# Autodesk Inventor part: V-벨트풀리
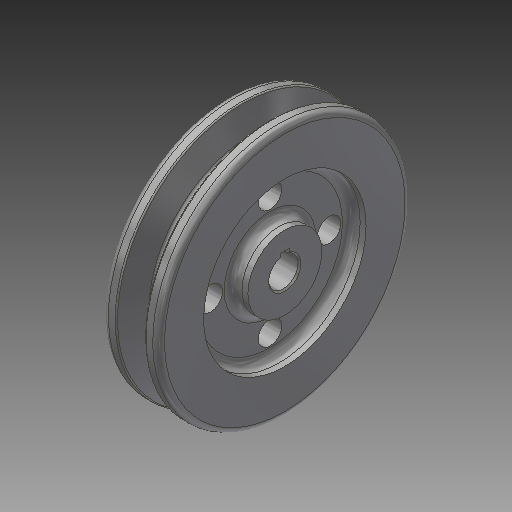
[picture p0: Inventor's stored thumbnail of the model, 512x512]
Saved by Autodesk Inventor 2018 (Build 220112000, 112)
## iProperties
Created: 2015-09
Part Number: V-벨트풀리
Material: 강철, 연강
Document SubType Name: Modeling
Designer: mduedu
Density: 1 g/cm^3
Appearance: 강철
Author: mduedu
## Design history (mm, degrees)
sketch "스케치1"
  geometry: L1 (-9.5, 0)-(9.5, 0); L2 (-9.5, 0)-(-9.5, 42.7); L3 (-9.5, 42.7)-(-4.877, 42.7); L4 (-4.877, 42.7)-(-1.953, 33.7); L5 (-1.953, 33.7)-(1.953, 33.7); L6 (1.953, 33.7)-(4.877, 42.7); L7 (4.877, 42.7)-(9.5, 42.7); L8 (9.5, 42.7)-(9.5, 0); L9 (0, 0)-(0, 33.7); L10 (-9.5, 40)-(9.5, 40); 3 further points
  constraints: 20 end point, 6 point on line, 3 perpendicular, 2 midpoint, 2 parallel, 2 symmetric about line, 1 coincident, 1 collinear, 1 equal length, 1 horizontal, 1 vertical, 1 vertical alignment
  dimensions: "d0" = 19 distance between parallel lines of L8 L2; "d5" = 6.3 distance between parallel lines of L5 L10; "d6" = 8 distance of point (4, 40) point (-4, 40); "d7" = 36 deg angle of L6 L4; "d40" = 2.7 distance between parallel lines of L10 L3; "d82" = 80 diameter of L10 L1; "d83" = 85.4 diameter of L3 L1 (derived)
revolve "회전1" sketch "스케치1" stored, may be unused: angle "d8" = 90 deg
sketch "스케치2"
  geometry: C1 r 12.5 at (0, 0); C2 r 27.5 at (0, 0); 1 further point
  constraints: 2 centre point, 2 coincident
  dimensions: "d9" = 25 diameter of C1; "d41" = 55 diameter of C2
extrude "돌출5" cut sketch "스케치2" distance "d42" = 5; taper "d43" = 0 deg
hole "구멍2" diameter "d46" = 10; stored, may be unused: countersink angle "d50" = 90 deg, drill point angle "d52" = 118 deg; dims "d47" = 6, "d48" = 4, "d49" = 2, "d51" = 8, "d84" = 10, "d85" = 10
sketch "스케치8"
  geometry: L1 (-1.5, 4.77)-(1.5, 4.77); L2 (1.5, 4.77)-(1.5, 6.4); L3 (1.5, 6.4)-(-1.5, 6.4); L4 (-1.5, 6.4)-(-1.5, 4.77); A1 r 5 centre (0, 0) between (-1.5, 4.77) and (1.5, 4.77) reference; 1 further point
  constraints: 8 end point, 2 parallel, 2 point on circle, 1 horizontal, 1 perpendicular
  dimensions: "d53" = 3 distance of L2.end L3.end; "d55" = 11.4 dimension on A1 L3
extrude "돌출6" cut sketch "스케치8" extent not by distance; stored distance "d56" = 5; taper "d57" = 0 deg
fillet "모깎기5" dims "d71" = 2, "d72" = 1, "d73" = 0.5
fillet "모깎기7" dims "d75" = 3
fillet "모깎기8" dims "d76" = 3
sketch "스케치10"
  geometry: C1 r 35 at (0, 0); 1 further point
  constraints: 1 centre point, 1 coincident, 1 other
  dimensions: "d77" = 70 diameter of C1
extrude "돌출8" join sketch "스케치10" distance "d80" = 0.5; taper "d81" = 0 deg
chamfer "모따기4" distance "d88" = 0.5; stored, may be unused: second distance "d89" = 2, angle "d90" = 45 deg
sketch "스케치11" dims "d91" = 40
  geometry: C1 r 4 at (0, 20); 2 further points
  constraints: 2 vertical alignment, 1 centre point, 1 coincident, 2 other
  dimensions: "d92" = 8 diameter of C1
extrude "돌출9" cut sketch "스케치11" extent not by distance; stored distance "d93" = 10; taper "d94" = 0 deg
node "솔리드1"
mirror "대칭2"
pattern_circular "원형 패턴2" dims angle "d96" = 360 deg
